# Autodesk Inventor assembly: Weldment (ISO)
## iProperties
Length Units: 11269
Angle Units: 11283
Time Units: 11279
Mass Units: 11290
Length Display Precision: 3
Angle Display Precision: 2
Part Number: Weldment (ISO)
Document SubType Name: Weldment
Created: 2002-06
Designer: smithga
Part Number: support de rail
Created: 2005-02
Designer: LEGERET Philippe
Material: Aluminum soudé-6061
Control State: 0
Master: False
Shininess: 64.0
Angle Units: 11279
Time Units: 11290
Mass Units: 11283
Compacted: True
Density: 0.0
Volumn: 0.0
Area: 0.0
PropertySet Name: Model Information
Author: LEGERET Philippe
